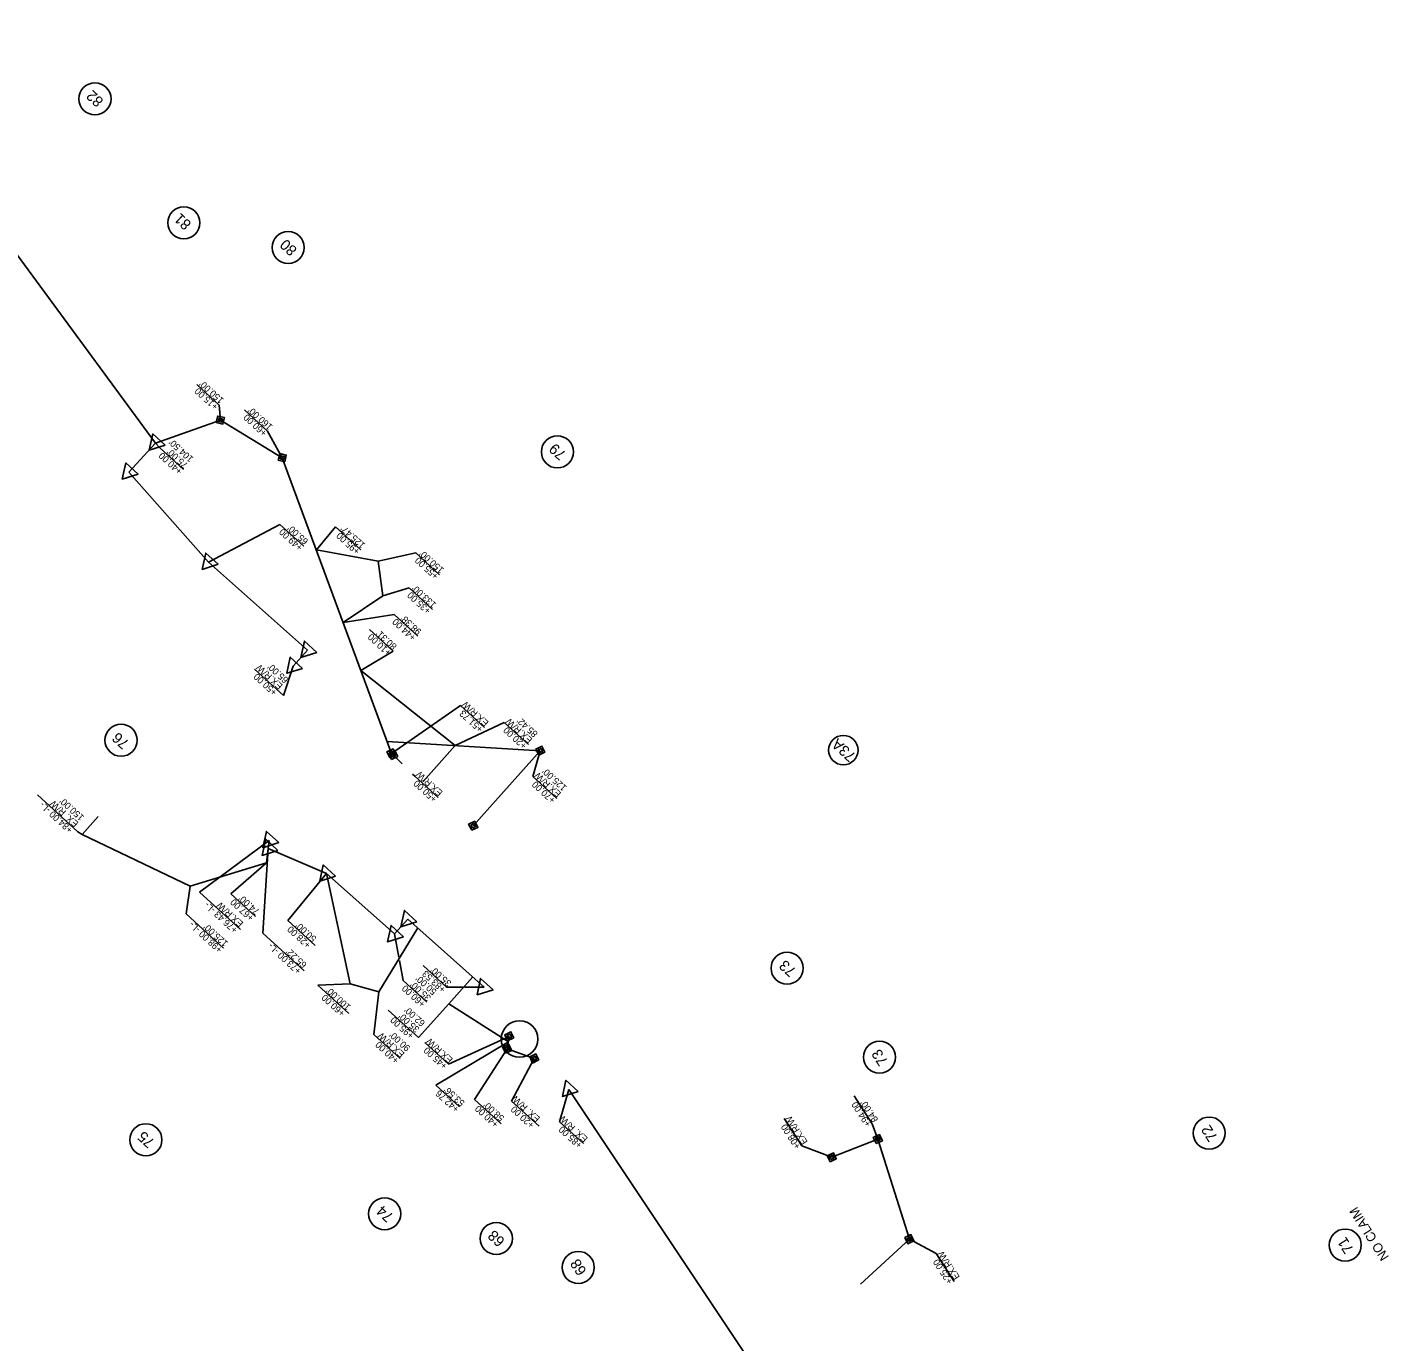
# Model space of a CAD drawing. Extents: x 474184 to 481900, y 489262 to 505659.
# Drawn here: x 476644 to 477663, y 500108 to 501092 of the extents above; entities that cross this region are included whole.
import ezdxf

# ---------------------------------------------------------------- set-up
doc = ezdxf.new("R2010")
doc.units = 0
for name, color, linetype in [('Prop Drainage Structure Drop Inlet Grate 2 Wide Slots and Sag Grates 840 22 CELL', 7, 'Continuous'), ('Prop Drainage Structure Outlet Berm Ditch 850 10 Label', 7, 'Continuous'), ('Prop Drainage Structure Pipe CSP 15in', 7, 'Continuous'), ('Prop Drainage Structure Pipe RCP 18in Class IV', 7, 'Continuous'), ('Prop Drainage Structure Pipe RCP 18in Class IV Label', 7, 'Continuous'), ('Prop Drainage Structure Pipe RCP 24in Class III', 7, 'Continuous'), ('Prop Drainage Structure Pipe Side Drain 15in Label', 7, 'Continuous'), ('Prop Drainage Structure Pipe Stub Out CELL', 7, 'Continuous'), ('Prop Drainage Structure Plot Symbol 50 Scale', 7, 'Continuous'), ('Prop Earthen Structure Base Ditch Lateral Detail Label', 7, 'Continuous'), ('Prop Earthen Structure False Sump CELL', 7, 'Continuous'), ('Prop Earthen Structure False Sump Label', 7, 'Continuous'), ('Sheet Plot Border Inside CELL', 7, 'Continuous'), ('Sheet Plot Border Outside CELL', 7, 'Continuous')]:
    doc.layers.add(name, color=color, linetype=linetype)

msp = doc.modelspace()

# ---------------------------------------------------------------- linework, layer by layer
at = {"layer": 'Prop Drainage Structure Drop Inlet Grate 2 Wide Slots and Sag Grates 840 22 CELL'}
for p, q in [((476788.7, 500798), (476740.3, 500780.7)), ((476835, 500769.8), (476788.7, 500798)), ((476916.7, 500548.6), (476835, 500769.8))]:
    msp.add_line(p, q, dxfattribs=at)
at = {"layer": 'Prop Drainage Structure Outlet Berm Ditch 850 10 Label'}
for p, q in [((477003.2, 500327.5), (477004.8, 500336.8)), ((477023.5, 500320.2), (477003.2, 500327.5)), ((477280.5, 500259.9), (477246, 500246.3)), ((477304.1, 500185), (477280.5, 500259.9))]:
    msp.add_line(p, q, dxfattribs=at)
at = {"layer": 'Prop Drainage Structure Pipe CSP 15in'}
for p, q in [((476694.9, 501038.4), (476694.9, 501038.4)), ((476761.4, 500945.6), (476761.4, 500945.6)), ((476839.4, 500927.2), (476839.4, 500927.2)), ((477040.8, 500774.2), (477040.8, 500774.2)), ((476714.4, 500558.4), (476714.4, 500558.4)), ((477254.7, 500551), (477254.7, 500551)), ((477212.6, 500387.8), (477212.6, 500387.8)), ((477281.7, 500321.2), (477281.7, 500321.2)), ((477528.3, 500264.4), (477528.3, 500264.4)), ((476733, 500259.4), (476733, 500259.4)), ((476911.6, 500204), (476911.6, 500204)), ((476995.1, 500185.5), (476995.1, 500185.5)), ((477630.1, 500180.6), (477630.1, 500180.6)), ((477056.4, 500163.9), (477056.4, 500163.9))]:
    msp.add_line(p, q, dxfattribs=at)
for centre, radius in [((476694.9, 501038.4), 12), ((476761.4, 500945.6), 12), ((476839.4, 500927.2), 12), ((477040.8, 500774.2), 12), ((476714.4, 500558.4), 12), ((477254.7, 500551), 11), ((477212.6, 500387.8), 12), ((477281.7, 500321.2), 12), ((477528.3, 500264.4), 12), ((476733, 500259.4), 12), ((476911.6, 500204), 12), ((476995.1, 500185.5), 12), ((477630.1, 500180.6), 12), ((477056.4, 500163.9), 12)]:
    msp.add_circle(centre, radius, dxfattribs=at)
at = {"layer": 'Prop Drainage Structure Pipe RCP 18in Class IV'}
for p, q in [((476788.7, 500798), (476788.7, 500798)), ((476740.3, 500780.7), (476740.3, 500780.7)), ((476835, 500769.8), (476835, 500769.8)), ((476720.2, 500759.1), (476720.2, 500759.1)), ((476779.9, 500691.6), (476779.9, 500691.6)), ((476853.8, 500625.7), (476853.8, 500625.7)), ((476843.2, 500613.8), (476843.2, 500613.8)), ((476916.7, 500548.6), (476916.7, 500548.6)), ((476824.7, 500477.5), (476824.7, 500477.5)), ((476825.3, 500483.3), (476825.3, 500483.3)), ((476867.9, 500458.2), (476867.9, 500458.2)), ((476928.6, 500424.2), (476928.6, 500424.2)), ((476918.6, 500413), (476918.6, 500413)), ((476985.6, 500373.2), (476985.6, 500373.2)), ((477004.8, 500336.8), (477004.8, 500336.8)), ((477003.2, 500327.5), (477003.2, 500327.5)), ((477023.5, 500320.2), (477023.5, 500320.2)), ((477049.4, 500297.1), (477049.4, 500297.1)), ((477280.5, 500259.9), (477280.5, 500259.9)), ((477246, 500246.3), (477246, 500246.3)), ((477304.1, 500185), (477304.1, 500185))]:
    msp.add_line(p, q, dxfattribs=at)
for points in [[(476747.3, 500779.2), (476735.4, 500775.4), (476738.1, 500787.6)], [(476727.2, 500757.5), (476715.3, 500753.8), (476718, 500766)], [(476787, 500690.1), (476775.1, 500686.3), (476777.8, 500698.5)], [(476860.8, 500624.1), (476848.9, 500620.4), (476851.6, 500632.6)], [(476850.2, 500612.2), (476838.3, 500608.5), (476841, 500620.7)], [(476832.4, 500481.8), (476820.5, 500478), (476823.1, 500490.2)], [(476831.8, 500475.9), (476819.9, 500472.2), (476822.6, 500484.4)], [(476874.9, 500456.7), (476863, 500452.9), (476865.7, 500465.1)], [(476935.6, 500422.6), (476923.7, 500418.8), (476926.4, 500431)], [(476925.6, 500411.4), (476913.7, 500407.6), (476916.4, 500419.8)], [(476992.7, 500371.7), (476980.8, 500367.9), (476983.4, 500380.1)], [(477056.4, 500295.5), (477044.5, 500291.8), (477047.2, 500304)]]:
    msp.add_lwpolyline(points, close=True, dxfattribs=at)
at = {"layer": 'Prop Drainage Structure Pipe RCP 18in Class IV Label'}
for points in [[(476785.6, 500796.1), (476786.7, 500801), (476791.7, 500799.9), (476790.6, 500795)], [(476787.2, 500797), (476787.7, 500799.5), (476790.2, 500799), (476789.6, 500796.5)], [(476832, 500767.9), (476833.1, 500772.9), (476838, 500771.8), (476836.9, 500766.8)], [(476833.5, 500768.9), (476834, 500771.3), (476836.5, 500770.8), (476836, 500768.3)], [(476915.5, 500545.2), (476913.3, 500549.8), (476917.9, 500552), (476920.1, 500547.4)], [(476916.1, 500546.9), (476915, 500549.2), (476917.3, 500550.3), (476918.4, 500548)], [(477003.6, 500333.4), (477001.4, 500338), (477006, 500340.2), (477008.2, 500335.7)], [(477004.2, 500335.1), (477003.1, 500337.4), (477005.4, 500338.5), (477006.5, 500336.2)], [(477002, 500324.1), (476999.8, 500328.7), (477004.3, 500330.9), (477006.6, 500326.3)], [(477002.6, 500325.8), (477001.5, 500328.1), (477003.8, 500329.2), (477004.9, 500326.9)], [(477022.3, 500316.8), (477020.1, 500321.4), (477024.7, 500323.7), (477026.9, 500319.1)], [(477022.9, 500318.5), (477021.8, 500320.8), (477024.1, 500322), (477025.2, 500319.7)], [(477279.3, 500256.5), (477277.1, 500261.1), (477281.7, 500263.3), (477283.9, 500258.7)], [(477279.9, 500258.2), (477278.8, 500260.5), (477281.1, 500261.6), (477282.2, 500259.3)], [(477244.8, 500242.9), (477242.6, 500247.5), (477247.2, 500249.7), (477249.4, 500245.1)], [(477245.4, 500244.6), (477244.3, 500246.9), (477246.6, 500248), (477247.7, 500245.7)], [(477302.9, 500181.6), (477300.7, 500186.2), (477305.2, 500188.4), (477307.5, 500183.8)], [(477303.5, 500183.3), (477302.4, 500185.6), (477304.7, 500186.7), (477305.8, 500184.4)]]:
    msp.add_lwpolyline(points, close=True, dxfattribs=at)
at = {"layer": 'Prop Drainage Structure Pipe RCP 24in Class III'}
msp.add_circle((477012.5, 500334.8), 13.7, dxfattribs=at)
at = {"layer": 'Prop Drainage Structure Pipe Side Drain 15in Label'}
for p, q in [((476740.3, 500780.7), (476511.3, 501092)), ((476740.3, 500780.7), (476720.2, 500759.1)), ((476720.2, 500759.1), (476779.9, 500691.6)), ((476853.8, 500625.7), (476779.9, 500691.6)), ((476853.8, 500625.7), (476843.2, 500613.8)), ((476824.5, 500477.3), (476825.3, 500483.3)), ((476868.2, 500458.7), (476824.5, 500477.3)), ((476868.2, 500458.7), (476919, 500413.4)), ((476919, 500413.4), (476929, 500424.6)), ((476986, 500373.7), (476929, 500424.6)), ((477222.8, 500036.8), (477049.4, 500297.1))]:
    msp.add_line(p, q, dxfattribs=at)
at = {"layer": 'Prop Drainage Structure Pipe Stub Out CELL'}
for p, q in [((476906.7, 500692.4), (476860.5, 500700.8)), ((476910.3, 500666.4), (476906.7, 500692.4)), ((476880.5, 500646.6), (476910.3, 500666.4)), ((476964.4, 500554.4), (476893.8, 500610.5)), ((476964.4, 500554.4), (476940.5, 500527.5)), ((476685.3, 500487.9), (476697.3, 500501.4)), ((476766.1, 500449.3), (476685.3, 500487.9)), ((476824.5, 500477.3), (476823.2, 500466.7)), ((476823.2, 500466.7), (476766.1, 500449.3)), ((476885.7, 500376.1), (476868.2, 500458.7)), ((476936.4, 500417.9), (476907.3, 500370.2)), ((476907.3, 500370.2), (476885.7, 500376.1)), ((476959.5, 500361.1), (476977.5, 500381.3)), ((477004.1, 500332.7), (476959.5, 500361.1))]:
    msp.add_line(p, q, dxfattribs=at)
at = {"layer": 'Prop Drainage Structure Plot Symbol 50 Scale'}
for p, q in [((476743.4, 500777.2), (476761.2, 500761)), ((476833.3, 500719.9), (476851.1, 500703.7)), ((476814.3, 500611.7), (476836, 500591.9)), ((476843.2, 500613.8), (476836, 500591.9)), ((476773, 500444.8), (476825.3, 500483.3)), ((476839.2, 500423.4), (476868.2, 500458.7)), ((476803.8, 500416.7), (476773, 500444.8)), ((476859.6, 500404.7), (476839.2, 500423.4)), ((476851.3, 500385.9), (476820.5, 500414)), ((476940.3, 500389.7), (476957.9, 500373.6)), ((476925.4, 500378.6), (476943.1, 500362.4)), ((477042.4, 500272.8), (477060.2, 500256.6))]:
    msp.add_line(p, q, dxfattribs=at)
for points in [[(476743.4, 500777.2), (476740.3, 500780.7)], [(476833.3, 500719.9), (476779.9, 500691.6)], [(476820.5, 500414), (476824.5, 500477.3)], [(476922.1, 500396.1), (476919, 500413.4)], [(476925.4, 500378.6), (476922.6, 500393.6)], [(476957.9, 500373.6), (476970.1, 500373.6)], [(476971.4, 500373.6), (476986, 500373.7)], [(477042.4, 500272.8), (477049.4, 500297.1)]]:
    msp.add_lwpolyline(points, dxfattribs=at)
at = {"layer": 'Prop Earthen Structure Base Ditch Lateral Detail Label'}
for p, q in [((476916.7, 500548.6), (476968.2, 500584.4)), ((476986.2, 500567.9), (476968.2, 500584.4)), ((476941.6, 500332.1), (476959.3, 500315.9)), ((476978.9, 500289.5), (476998.7, 500271.4)), ((477006.5, 500288.3), (477027.1, 500269.5)), ((477276.2, 500271.4), (477262.8, 500292.3)), ((477223.6, 500254.8), (477210.4, 500275.3)), ((477280.5, 500259.9), (477276.2, 500271.4)), ((477246, 500246.3), (477223.6, 500254.8)), ((477324.2, 500174.2), (477304.1, 500185)), ((477337.6, 500153.4), (477324.2, 500174.2))]:
    msp.add_line(p, q, dxfattribs=at)
for points in [[(476959.3, 500315.9), (477004.8, 500336.8)], [(476978.9, 500289.5), (477003.2, 500327.5)], [(477006.5, 500288.3), (477023.5, 500320.2)]]:
    msp.add_lwpolyline(points, dxfattribs=at)
at = {"layer": 'Prop Earthen Structure False Sump CELL'}
for p, q in [((476771, 500824.6), (476787.9, 500809.2)), ((476806.7, 500805.7), (476824, 500789.8))]:
    msp.add_line(p, q, dxfattribs=at)
for points in [[(476787.9, 500809.2), (476788.7, 500798)], [(476824, 500789.8), (476835, 500769.8)]]:
    msp.add_lwpolyline(points, dxfattribs=at)
at = {"layer": 'Prop Earthen Structure False Sump Label'}
for p, q in [((476874.9, 500718.1), (476893.8, 500700.9)), ((476934.9, 500698.6), (476952.6, 500682.3)), ((476929.8, 500672.5), (476947.5, 500656.3)), ((476918.6, 500652.4), (476936.3, 500636.2)), ((476900.2, 500641.2), (476917.9, 500625)), ((476893.8, 500610.5), (476917.9, 500625)), ((477000.9, 500571.8), (476964.4, 500554.4)), ((477000.9, 500571.8), (477019.2, 500555.1)), ((476651.8, 500517.5), (476682.1, 500489.8)), ((476682.1, 500489.8), (476685.3, 500487.9)), ((476796.5, 500443.5), (476815.1, 500426.5)), ((476763.1, 500428.4), (476791.1, 500402.8)), ((476885.7, 500376.1), (476861.6, 500375.1)), ((476861.6, 500375.1), (476884.8, 500353.9)), ((476903.4, 500338.3), (476907.3, 500370.2)), ((476914.3, 500356.4), (476936.8, 500335.9)), ((476903.4, 500338.3), (476923.2, 500320.2)), ((476949.8, 500300.3), (476967.5, 500284.1))]:
    msp.add_line(p, q, dxfattribs=at)
for points in [[(476874.9, 500718.1), (476860.5, 500700.8)], [(476934.9, 500698.6), (476906.7, 500692.4)], [(476929.8, 500672.5), (476910.3, 500666.4)], [(476918.6, 500652.4), (476880.5, 500646.6)], [(476796.5, 500443.5), (476823.2, 500466.7)], [(476763.1, 500428.4), (476766.1, 500449.3)], [(476936.8, 500335.9), (476959.5, 500361.1)], [(476949.8, 500300.3), (477004.1, 500332.7)]]:
    msp.add_lwpolyline(points, dxfattribs=at)
at = {"layer": 'Sheet Plot Border Inside CELL'}
for p, q in [((477028, 500550.6), (476913.5, 500557.4)), ((476977.9, 500494.4), (477028, 500550.6)), ((477028, 500550.6), (477022.4, 500531.2)), ((477028, 500550.6), (477028, 500550.6)), ((476918, 500547.4), (476918, 500547.4)), ((476918, 500547.4), (476924.7, 500540.8)), ((476932.5, 500533), (476934.2, 500531.4)), ((476951.6, 500515.5), (476934.2, 500531.4)), ((477040.4, 500514.8), (477022.4, 500531.2)), ((476977.9, 500494.4), (476977.9, 500494.4))]:
    msp.add_line(p, q, dxfattribs=at)
for points in [[(476916.8, 500544), (476914.6, 500548.6), (476919.2, 500550.8), (476921.4, 500546.3)], [(476917.4, 500545.7), (476916.3, 500548), (476918.6, 500549.1), (476919.7, 500546.9)], [(477026.9, 500547.2), (477024.6, 500551.8), (477029.2, 500554), (477031.4, 500549.4)], [(477027.5, 500548.9), (477026.3, 500551.2), (477028.6, 500552.3), (477029.7, 500550)], [(476976.7, 500491), (476974.4, 500495.5), (476979, 500497.8), (476981.3, 500493.2)], [(476977.3, 500492.7), (476976.2, 500495), (476978.4, 500496.1), (476979.6, 500493.8)]]:
    msp.add_lwpolyline(points, close=True, dxfattribs=at)
at = {"layer": 'Sheet Plot Border Outside CELL'}
msp.add_line((477304.1, 500185), (477267.6, 500151.3), dxfattribs=at)

# ---------------------------------------------------------------- texts
at = {"layer": 'Prop Drainage Structure Pipe CSP 15in'}
for s, height, rotation, p in [('82', 8, 137.58, (476701.8, 501037.4)), ('81', 8, 137.58, (476767.5, 500945.4)), ('80', 8, 137.58, (476846.6, 500926)), ('79', 8, 137.58, (477047.9, 500773.2)), ('76', 8, 137.58, (476721, 500556.9)), ('73A', 8, 137.58, (477264.6, 500547.4)), ('73', 8, 138.4268, (477220, 500386.6)), ('73', 8, 122.6818, (477288.4, 500318)), ('75', 8, 137.58, (476740.1, 500258.4)), ('72', 8, 122.6818, (477535, 500261.3)), ('74', 8, 137.58, (476918.8, 500202.8)), ('NO CLAIM', 7, 122.6818, (477663.1, 500171.7)), ('68', 8, 137.58, (477002.1, 500184.4)), ('71', 8, 122.6818, (477636.8, 500177.4)), ('68', 8, 122.6818, (477063, 500161.1))]:
    msp.add_text(s, height=height, rotation=rotation, dxfattribs=at).set_placement(p)
at = {"layer": 'Prop Drainage Structure Plot Symbol 50 Scale'}
for s, p in [("104.50'", (476769, 500769.6)), ('+40.00', (476760.6, 500760.4)), ("75.00'", (476764.8, 500765)), ('+49.00', (476850.7, 500703.3)), ("65.00'", (476854.9, 500707.9)), ('EX.R/W', (476835.8, 500599.6)), ("65.00'", (476840, 500604.2)), ('+50.00', (476831.6, 500595)), ('+76.43 -L-', (476802.1, 500417.1)), ('EX.R/W', (476806.3, 500421.8)), ('+28.00', (476856.8, 500405.9)), ("50.00'", (476861, 500410.5)), ('+73.00 -L-', (476849.6, 500386.4)), ("65.22'", (476853.8, 500391)), ('+83.53', (476957.7, 500372.6)), ("35.00'", (476961.9, 500377.2)), ("35.00'", (476946.7, 500366.3)), ("50.00'", (476950.9, 500370.9)), ('+60.00', (476942.5, 500361.7)), ('EX. R/W', (477064, 500260.7)), ('+85.00', (477059.8, 500256.1))]:
    msp.add_text(s, height=5, rotation=137.58, dxfattribs=at).set_placement(p)
at = {"layer": 'Prop Earthen Structure Base Ditch Lateral Detail Label'}
for s, rotation, p in [('+51.73', 137.58, (476985.6, 500567.4)), ('EX.R/W', 137.58, (476989.8, 500572)), ('EX.R/W', 137.58, (476963, 500319.9)), ('+45.00', 137.58, (476958.8, 500315.3)), ('+40.00', 137.58, (476997.2, 500271.7)), ("58.00'", 137.58, (477001.5, 500276.3)), ('EX. R/W', 137.58, (477028.3, 500275.8)), ('+20.00', 137.58, (477024, 500271.2)), ('+94.00 ', 122.6818, (477275.8, 500271.1)), ("84.00' ", 122.6818, (477281, 500274.5)), ('EX.R/W', 122.6818, (477228.2, 500257.8)), ('+08.00 ', 122.6818, (477223, 500254.4)), ('EX.R/W', 122.6818, (477342, 500156.7)), ('+25.00 ', 122.6818, (477336.8, 500153.3))]:
    msp.add_text(s, height=5, rotation=rotation, dxfattribs=at).set_placement(p)
at = {"layer": 'Prop Earthen Structure False Sump CELL'}
for s, p in [("150.00'", (476791.7, 500813.4)), ('+15.00', (476787.5, 500808.7)), ("160.00'", (476828.2, 500793.6)), ('+60.00', (476824, 500789))]:
    msp.add_text(s, height=5, rotation=137.58, dxfattribs=at).set_placement(p)
at = {"layer": 'Prop Earthen Structure False Sump Label'}
for s, p in [('+95.00', (476893.5, 500700.5)), ("125.47'", (476897.5, 500705)), ('+55.00', (476952.3, 500682)), ("150.00'", (476956.3, 500686.4)), ("133.00'", (476950.7, 500660.4)), ('+35.00', (476946.6, 500656)), ("98.38'", (476939.5, 500640.4)), ("80.31'", (476921.1, 500629.2)), ('+44.00', (476935.4, 500636)), ('+10.00', (476917, 500624.7)), ('EX.R/W', (477022.5, 500559.3)), ("85.42'", (477026.5, 500563.8)), ('+20.00', (477018.4, 500554.9)), ('+84.00 -L-', (476678.8, 500492)), ('EX. R/W', (476683, 500496.6)), ("150.00'", (476687.2, 500501.2)), ('+67.00', (476814.2, 500426.2)), ("74.00'", (476818.4, 500430.9)), ('+98.00 -L-', (476790.7, 500402.4)), ("125.00'", (476794.9, 500407)), ('+60.00', (476882.4, 500354.8)), ("100.00'", (476886.6, 500359.4)), ("62.00'", (476942.3, 500347.3)), ('+95.00', (476933.9, 500338)), ("35.00'", (476938.1, 500342.7)), ('EX.R/W', (476926.9, 500324.1)), ("90.00'", (476931.2, 500328.7)), ('+40.00', (476922.7, 500319.5)), ('+42.76', (476967.7, 500283)), ("53.56'", (476971.9, 500287.6))]:
    msp.add_text(s, height=5, rotation=137.58, dxfattribs=at).set_placement(p)
at = {"layer": 'Sheet Plot Border Inside CELL'}
for s, p in [('+50.00', (476951.2, 500515.1)), ('EX.R/W', (476955.4, 500519.7)), ('EX.R/W', (477044, 500518.9)), ("125.00' ", (477048.2, 500523.5)), ('+70.00', (477039.8, 500514.3))]:
    msp.add_text(s, height=5, rotation=137.58, dxfattribs=at).set_placement(p)

doc.saveas('drawing.dxf')
